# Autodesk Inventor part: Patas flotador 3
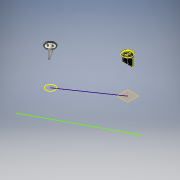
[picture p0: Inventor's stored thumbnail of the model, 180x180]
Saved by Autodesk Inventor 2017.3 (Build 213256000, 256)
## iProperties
Part Number: Patas flotador 3
Material: Plástico ABS
Document SubType Name: Modeling
Designer: PABLO HERNANDEZ
Density: 1.06 g/cm^3
Appearance: Suave - Blanco
Mass: 4.28877 g
Surface Area: 39.5254 cm^2
Volume: 4.04601 cm^3
Author: M.RICO
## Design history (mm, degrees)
sketch "Boceto1"
  geometry: C1 r 16 at (0, 0); 1 further point
  constraints: 1 centre point, 1 coincident
  dimensions: "d0" = 32 diameter of C1
extrude "Extrusión1" new body sketch "Boceto1" distance "d1" = 1; taper "d2" = 0 deg; dims "d93" = 1, "d94" = 0
sketch "Boceto2"
  geometry: C1 r 16 at (0, 0); C2 r 15 at (0, 0); C3 r 14 at (0, 0); 1 further point
  constraints: 3 centre point, 1 coincident
  dimensions: "d3" = 1 radial gap between concentric circles of C1 C2; "d4" = 1 radial gap between concentric circles of C2 C3
extrude "Extrusión2" join sketch "Boceto2" distance "d5" = 3; taper "d6" = 0 deg
sketch "Boceto3"
  geometry: C1 r 15 at (0, 0); C2 r 14 at (0, 0); 1 further point
  constraints: 2 centre point, 1 coincident
  dimensions: "d7" = 1 radial gap between concentric circles of C1 C2; "d123" = 30 diameter of C1
extrude "Extrusión3" join sketch "Boceto3" distance "d8" = 2; taper "d9" = 0 deg
sketch "Boceto4"
  geometry: C1 r 16 at (0, 0); 1 further point
  constraints: 1 centre point, 1 coincident
extrude "Extrusión4" cut sketch "Boceto4" distance "d10" = 0.5; taper "d11" = 0 deg
sketch "Boceto7"
  geometry: L1 (1.5, -15.93)-(1.5, 15.93); L2 (-1.5, -15.93)-(-1.5, 15.93); A1 r 16 centre (0, 0) between (1.5, 15.93) and (-1.5, 15.93); A2 r 16 centre (0, 0) between (-1.5, -15.93) and (1.5, -15.93); 2 further points
  constraints: 4 end point, 4 point on circle, 2 centre point, 1 coincident
extrude "Extrusión7" join sketch "Boceto7" distance "d63" = 25; taper "d64" = 0 deg
fillet "Empalme2" dims "d95" = 3
fillet "Empalme3" dims "d96" = 0.5
sketch "Boceto13"
  geometry: C1 r 1.2 at (-6, 0) reference; C2 r 1.75 at (-6, 0); C3 r 1.2 at (6, 0) reference; C4 r 1.75 at (6, 0); 1 further point
  constraints: 2 centre point, 2 coincident
  dimensions: "d118" = 3.5 diameter of C2; "d119" = 3.5 diameter of C4
extrude "Extrusión10" join sketch "Boceto13" distance "d120" = 3; taper "d121" = 0 deg
fillet "Empalme4" dims "d122" = 1
sketch "Boceto14"
  geometry: 1 further point
sketch "Boceto15"
  geometry: C1 r 1.2 at (6, 0) reference; C2 r 2.5 at (6, 0); C3 r 1.2 at (-6, 0) reference; C4 r 2.5 at (-6, 0); 1 further point
  constraints: 2 centre point, 2 coincident
  dimensions: "d124" = 5 diameter of C2; "d125" = 5 diameter of C4
extrude "Extrusión11" cut sketch "Boceto15" distance "d126" = 10; taper "d127" = 0 deg
hole "Agujero7" diameter "d151" = 2.4; stored, may be unused: countersink angle "d155" = 90 deg, drill point angle "d157" = 118 deg; dims "d149" = 10, "d150" = 10, "d152" = 6, "d153" = 4, "d154" = 2, "d156" = 8
hole "Agujero8" diameter "d160" = 2.4; stored, may be unused: countersink angle "d164" = 90 deg, drill point angle "d166" = 118 deg; dims "d158" = 10, "d159" = 10, "d161" = 6, "d162" = 4, "d163" = 2, "d165" = 8
node "Eje de trabajo1"
feature "Desplazar cuerpo1"
feature "Compuesta1"
feature "Desplazar cuerpo2"
node "Eje de trabajo2"
feature "Desplazar cuerpo3"
node "Plano de trabajo6"
sketch "Boceto27"
  geometry: L1 (0, 0)-(-149.324, -102.291); L2 (-134.431, -229.557)-(132.044, -87.232); C1 r 14 at (-149.324, -102.291) reference
  constraints: 4 end point
node "Sólido1"
node "Sup1"
other parameters: "sa_0" = 4, "d167" = 90 deg, "d168" = -149.324, "d169" = -102.291, "d170" = 0, "d171" = 9.86699
